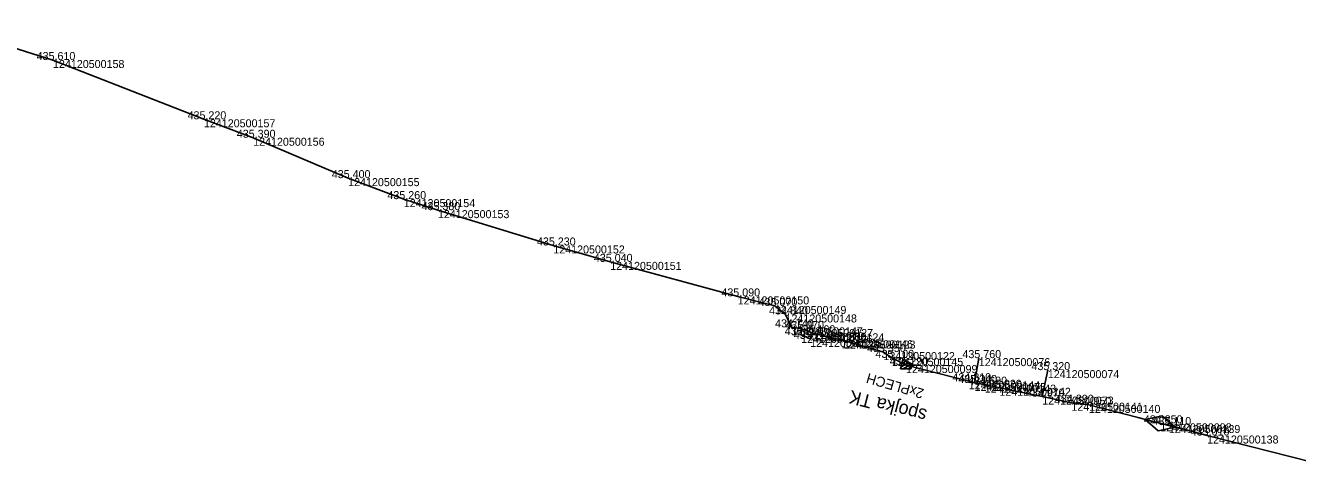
# Model space of a CAD drawing. Extents: x -637342 to -635997, y -1153616 to -1153154.
# Drawn here: x -636675.3 to -636484.6, y -1153447.2 to -1153380.9 of the extents above; entities that cross this region are included whole.
import ezdxf

# ---------------------------------------------------------------- set-up
doc = ezdxf.new("R2010")
doc.units = 0
for name, color, linetype in [('Vrstva 28', 7, 'Continuous'), ('Vrstva 32', 7, 'Continuous'), ('Vrstva 34', 7, 'Continuous'), ('Vrstva 60', 7, 'Continuous'), ('Vrstva 61', 7, 'Continuous')]:
    doc.layers.add(name, color=color, linetype=linetype)

msp = doc.modelspace()

# ---------------------------------------------------------------- linework, layer by layer
at = {"layer": 'Vrstva 28'}
for p, q in [((-636533.01, -1153434.52), (-636532.39, -1153430.79)), ((-636522.88, -1153436.56), (-636522.04, -1153432.59)), ((-636508.57, -1153439.7), (-636501.81, -1153441.44)), ((-636507.44, -1153439.99), (-636504.9, -1153439.44)), ((-636505.48, -1153441.7), (-636507.44, -1153439.99)), ((-636504.9, -1153439.44), (-636502.94, -1153441.15)), ((-636502.94, -1153441.15), (-636505.48, -1153441.7))]:
    msp.add_line(p, q, dxfattribs=at)
for points in [[(-636479.26, -1153447.21), (-636498.16, -1153442.4), (-636503.89, -1153440.83), (-636505.19, -1153440.57), (-636515.87, -1153437.81), (-636518.51, -1153437.48), (-636522.88, -1153436.56), (-636529.3, -1153435.24), (-636531.5, -1153434.77), (-636533.01, -1153434.52), (-636533.89, -1153434.25), (-636543.3, -1153431.83), (-636545.43, -1153430.75), (-636546.69, -1153429.88), (-636552.59, -1153428.17), (-636552.98, -1153428.11), (-636557.26, -1153427.06), (-636558.95, -1153426.42), (-636560.48, -1153426.17), (-636561.37, -1153424.24), (-636562.95, -1153422.97), (-636568.53, -1153421.53), (-636587.65, -1153416.35), (-636596.18, -1153413.89), (-636613.48, -1153408.59), (-636618.6, -1153406.94), (-636626.94, -1153403.79), (-636641.18, -1153397.73), (-636648.56, -1153394.96), (-636671.19, -1153386.07), (-636687.67, -1153380.88)], [(-636557.26, -1153427.06), (-636557.67, -1153427.9), (-636559.03, -1153427.32), (-636558.95, -1153426.42)]]:
    msp.add_lwpolyline(points, dxfattribs=at)
at = {"layer": 'Vrstva 32'}
for p, q in [((-636543.76, -1153430.93), (-636544.14, -1153432.39)), ((-636544.14, -1153432.39), (-636542.58, -1153432.4)), ((-636542.87, -1153431.42), (-636544.07, -1153432.13)), ((-636543.28, -1153431.19), (-636543.93, -1153431.58)), ((-636543.69, -1153430.97), (-636543.78, -1153431.03)), ((-636542.39, -1153431.68), (-636543.76, -1153430.93)), ((-636542.45, -1153431.64), (-636543.73, -1153432.4)), ((-636542.52, -1153432.15), (-636542.95, -1153432.4)), ((-636542.58, -1153432.4), (-636542.39, -1153431.68))]:
    msp.add_line(p, q, dxfattribs=at)
at = {"layer": 'Vrstva 34'}
msp.add_line((-636546.69, -1153429.88), (-636552.59, -1153428.17), dxfattribs=at)
at = {"layer": 'Vrstva 60'}
for p, q in [((-636671.19, -1153386.07), (-636671.19, -1153386.07)), ((-636648.56, -1153394.96), (-636648.56, -1153394.96)), ((-636641.18, -1153397.73), (-636641.18, -1153397.73)), ((-636626.94, -1153403.79), (-636626.94, -1153403.79)), ((-636618.6, -1153406.94), (-636618.6, -1153406.94)), ((-636613.48, -1153408.59), (-636613.48, -1153408.59)), ((-636596.18, -1153413.89), (-636596.18, -1153413.89)), ((-636587.65, -1153416.35), (-636587.65, -1153416.35)), ((-636568.53, -1153421.53), (-636568.53, -1153421.53)), ((-636562.95, -1153422.97), (-636562.95, -1153422.97)), ((-636561.37, -1153424.24), (-636561.37, -1153424.24)), ((-636560.48, -1153426.17), (-636560.48, -1153426.17)), ((-636558.95, -1153426.42), (-636558.95, -1153426.42)), ((-636559.03, -1153427.32), (-636559.03, -1153427.32)), ((-636557.67, -1153427.9), (-636557.67, -1153427.9)), ((-636557.26, -1153427.06), (-636557.26, -1153427.06)), ((-636552.98, -1153428.11), (-636552.98, -1153428.11)), ((-636552.59, -1153428.17), (-636552.59, -1153428.17)), ((-636546.69, -1153429.88), (-636546.69, -1153429.88)), ((-636545.43, -1153430.75), (-636545.43, -1153430.75)), ((-636543.3, -1153431.83), (-636543.3, -1153431.83)), ((-636532.39, -1153430.79), (-636532.39, -1153430.79)), ((-636533.89, -1153434.25), (-636533.89, -1153434.25)), ((-636522.04, -1153432.59), (-636522.04, -1153432.59)), ((-636533.01, -1153434.52), (-636533.01, -1153434.52)), ((-636531.5, -1153434.77), (-636531.5, -1153434.77)), ((-636529.3, -1153435.24), (-636529.3, -1153435.24)), ((-636522.88, -1153436.56), (-636522.88, -1153436.56)), ((-636518.51, -1153437.48), (-636518.51, -1153437.48)), ((-636515.87, -1153437.81), (-636515.87, -1153437.81)), ((-636505.19, -1153440.57), (-636505.19, -1153440.57)), ((-636503.89, -1153440.83), (-636503.89, -1153440.83)), ((-636498.16, -1153442.4), (-636498.16, -1153442.4))]:
    msp.add_line(p, q, dxfattribs=at)

# ---------------------------------------------------------------- texts
at = {"layer": 'Vrstva 32'}
msp.add_text('spojka TK', height=2, rotation=165.5057, dxfattribs=at).set_placement((-636540.02, -1153438.55))
at = {"layer": 'Vrstva 34'}
msp.add_text('2xPLECH', height=1.5, rotation=163.8368, dxfattribs=at).set_placement((-636540.51, -1153435.47))
at = {"layer": 'Vrstva 60'}
for s, p in [('124120500158', (-636671.19, -1153387.27)), ('124120500157', (-636648.56, -1153396.16)), ('124120500156', (-636641.18, -1153398.93)), ('124120500155', (-636626.94, -1153404.99)), ('124120500154', (-636618.6, -1153408.14)), ('124120500153', (-636613.48, -1153409.79)), ('124120500152', (-636596.18, -1153415.09)), ('124120500151', (-636587.65, -1153417.55)), ('124120500150', (-636568.53, -1153422.73)), ('124120500149', (-636562.95, -1153424.17)), ('124120500148', (-636561.37, -1153425.44)), ('124120500147', (-636560.48, -1153427.37)), ('124120500127', (-636558.95, -1153427.62)), ('124120500126', (-636559.03, -1153428.52)), ('124120500125', (-636557.67, -1153429.1)), ('124120500124', (-636557.26, -1153428.26)), ('124120500146', (-636552.98, -1153429.31)), ('124120500123', (-636552.59, -1153429.37)), ('124120500122', (-636546.69, -1153431.08)), ('124120500145', (-636545.43, -1153431.95)), ('124120500099', (-636543.3, -1153433.03)), ('124120500076', (-636532.39, -1153431.99)), ('124120500144', (-636533.89, -1153435.45)), ('124120500074', (-636522.04, -1153433.79)), ('124120500075', (-636533.01, -1153435.72)), ('124120500143', (-636531.5, -1153435.97)), ('124120500142', (-636529.3, -1153436.44)), ('124120500073', (-636522.88, -1153437.76)), ('124120500141', (-636518.51, -1153438.68)), ('124120500140', (-636515.87, -1153439.01)), ('124120500098', (-636505.19, -1153441.77)), ('124120500139', (-636503.89, -1153442.03)), ('124120500138', (-636498.16, -1153443.6))]:
    msp.add_text(s, height=1.2, dxfattribs=at).set_placement(p)
at = {"layer": 'Vrstva 61'}
for s, p in [('435.610', (-636673.64, -1153386.07)), ('435.220', (-636651.01, -1153394.96)), ('435.390', (-636643.63, -1153397.73)), ('435.400', (-636629.39, -1153403.79)), ('435.260', (-636621.05, -1153406.94)), ('435.380', (-636615.93, -1153408.59)), ('435.230', (-636598.63, -1153413.89)), ('435.040', (-636590.1, -1153416.35)), ('435.090', (-636570.98, -1153421.53)), ('435.070', (-636565.4, -1153422.97)), ('434.840', (-636563.82, -1153424.24)), ('434.740', (-636562.93, -1153426.17)), ('435.210', (-636561.48, -1153427.32)), ('435.070', (-636561.4, -1153426.42)), ('435.220', (-636560.12, -1153427.9)), ('435.160', (-636559.71, -1153427.06)), ('434.970', (-636555.43, -1153428.11)), ('435.200', (-636555.04, -1153428.17)), ('435.350', (-636549.14, -1153429.88)), ('435.100', (-636547.88, -1153430.75)), ('435.760', (-636534.84, -1153430.79)), ('435.290', (-636545.75, -1153431.83)), ('435.320', (-636524.49, -1153432.59)), ('434.810', (-636536.34, -1153434.25)), ('435.340', (-636535.46, -1153434.52)), ('434.690', (-636533.95, -1153434.77)), ('435.020', (-636531.75, -1153435.24)), ('434.970', (-636525.33, -1153436.56)), ('434.890', (-636520.96, -1153437.48)), ('434.950', (-636518.32, -1153437.81)), ('434.850', (-636507.64, -1153440.57)), ('435.110', (-636506.34, -1153440.83)), ('435.010', (-636500.61, -1153442.4))]:
    msp.add_text(s, height=1.2, dxfattribs=at).set_placement(p)

doc.saveas('drawing.dxf')
